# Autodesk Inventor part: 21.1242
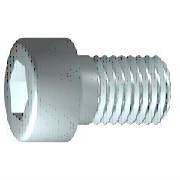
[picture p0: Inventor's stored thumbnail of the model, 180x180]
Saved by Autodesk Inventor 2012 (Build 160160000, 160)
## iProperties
Created: 2006-02
Part Number: 21.1242
Material: Steel, Mild
Description: M6X25 SHCS
Document SubType Name: Modeling
Standard: DIN 7984
Designer: Andy Moles
Standards Organization: DIN
Language: en-US
Size Designation: M6 x 25
Categories: <MemberInstance><Categories><Category DisplayName="Fasteners" InternalName="e4da775c-781d-43d5-af7c-5136215cf5a6" Mnemonic="FSTN"><Category DisplayName="Bolts"
Density: 7.86 g/cm^3
Mass: 7.59699 g
Surface Area: 7.83808 cm^2
Volume: 0.966539 cm^3
Vendor: S
Author: Andy Moles
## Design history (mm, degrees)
body "Solid1"
workplane "Work Plane1"
revolve "Body" stored, may be unused: angle "d10" = 90 deg
sketch "Sketch2"
  geometry: L1 (0, -6)-(0, 8) reference; L2 (-6, 0)-(8, 0) reference; L3 (2.309, 0)-(1.155, -2); L4 (1.155, -2)-(-1.155, -2); L5 (-1.155, -2)-(-2.309, 0); L6 (-2.309, 0)-(-1.155, 2); L7 (-1.155, 2)-(1.155, 2); L8 (1.155, 2)-(2.309, 0); 2 further points
  constraints: 12 end point, 1 coincident, 1 horizontal alignment, 1 point on line, 12 other
extrude "Slot" join sketch "Sketch2" stored distance "d11" = 10; taper "d12" = 0 deg
fillet "Fillet1" dims "d17" = 0.6 (= RR)
feature "Thread" dims "d13" = 25, "d14" = 0
chamfer "Chamfer1" distance "d15" = 0.61345 (= -0.5 x SPD + 0.5 x GD); stored, may be unused: second distance "d16" = 0.61345 (= GUL), angle "d27" = 45 deg
sketch "Sketch1"
  geometry: L1 (0.333, 0)-(25, 0); L2 (25, 0)-(25, 3); L3 (25, 3)-(3, 3); L4 (3, 3)-(2.386, 3); L5 (2.386, 3)-(0, 3); L6 (0, 3)-(0, 5); L7 (0, 5)-(-4, 5); L8 (-4, 5)-(-4, 2.309); L9 (-4, 2.309)-(-1, 2.309); L10 (-1, 2.309)-(0.333, 0); L11 (-6.9, 0)-(33.7, 0) reference; L12 (0, -0.5)-(0, 6.5) reference; L13 (3, 3)-(0, 3)
  constraints: 22 end point, 6 parallel, 2 collinear, 2 perpendicular, 1 horizontal, 1 midpoint
  dimensions: "d1" = 22 distance from line of L3.end L2 (= GEL); "d2" = 0.61355 distance of L4.end L3.end (computed from GAL); "d3" = 4 distance between parallel lines of L8 L6 (= KOH); "d4" = 3 distance of L8.end L9.end (= INTI); "d5" = 60 deg angle of L10 L1; "d6" = 6 diameter of L3 L1 (= GD); "d7" = 6 diameter of L5 L1 (= BDM); "d8" = 4.6188 diameter of L9 L1 (= 1.1547 x SW); "d9" = 10 diameter of L7 L1 (= KOD); "d26" = 25 distance between parallel lines of L12 L2 (= NLG)
other parameters: "GD" = 6 (= NND) [user parameter; used in 2 equation terms], "NLG" = 25 [user parameter; used in 1 equation term], "GEL" = 22 [user parameter; used in 1 equation term], "KOD" = 10 [user parameter; used in 1 equation term], "KOH" = 4 [user parameter; used in 1 equation term], "INTI" = 3 [user parameter; used in 1 equation term], "GAL" = 0.61345 (= 0.61345 x PTC) [user parameter; used in 1 equation term], "GUL" = 0.61345 (= 0.61345 x PTC) [user parameter; used in 1 equation term], "BDM" = 6 (= NND) [user parameter; used in 1 equation term], "SW" = 4 [user parameter; used in 2 equation terms], "RR" = 0.6 [user parameter; used in 1 equation term], "SPD" = 4.7731 (= NND - 1.2269 x PTC) [user parameter; used in 1 equation term], "d19" = 0, "d28" = 0, "d29" = 0, "TOA" = 30 deg [user parameter], "GD1" = 4.7731 (= THREADDIA - 1.2269 x PTC) [user parameter], "THREADDIA" = 6 [user parameter; used in 1 equation term], "FAWI" = 45 deg [user parameter], "ANG" = 120 deg [user parameter], "PTC" = 1 [user parameter; used in 5 equation terms], "NND" = 6 [user parameter; used in 3 equation terms], "E0" = 4.62 (= 1.155 x SW) [user parameter]
